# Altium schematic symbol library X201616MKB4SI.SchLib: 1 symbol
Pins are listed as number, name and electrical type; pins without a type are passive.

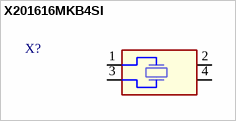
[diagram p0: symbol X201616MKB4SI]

## X201616MKB4SI
designator X?  (value not drawn)
OUT HERE OSCILLATING; Manufacturer_Name: Epson; Manufacturer_Part_Number: Q22FA12800400
footprint X201616MKB4SI
pins: 1, 2 (power), 3, 4 (power)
